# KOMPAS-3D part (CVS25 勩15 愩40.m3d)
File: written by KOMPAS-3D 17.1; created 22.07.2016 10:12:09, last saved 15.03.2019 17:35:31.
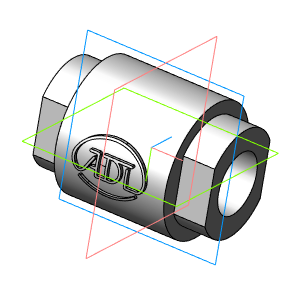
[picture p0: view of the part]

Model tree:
1. Операция без истории:2  (labels: Сталь 20  ГОСТ 1050-88)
